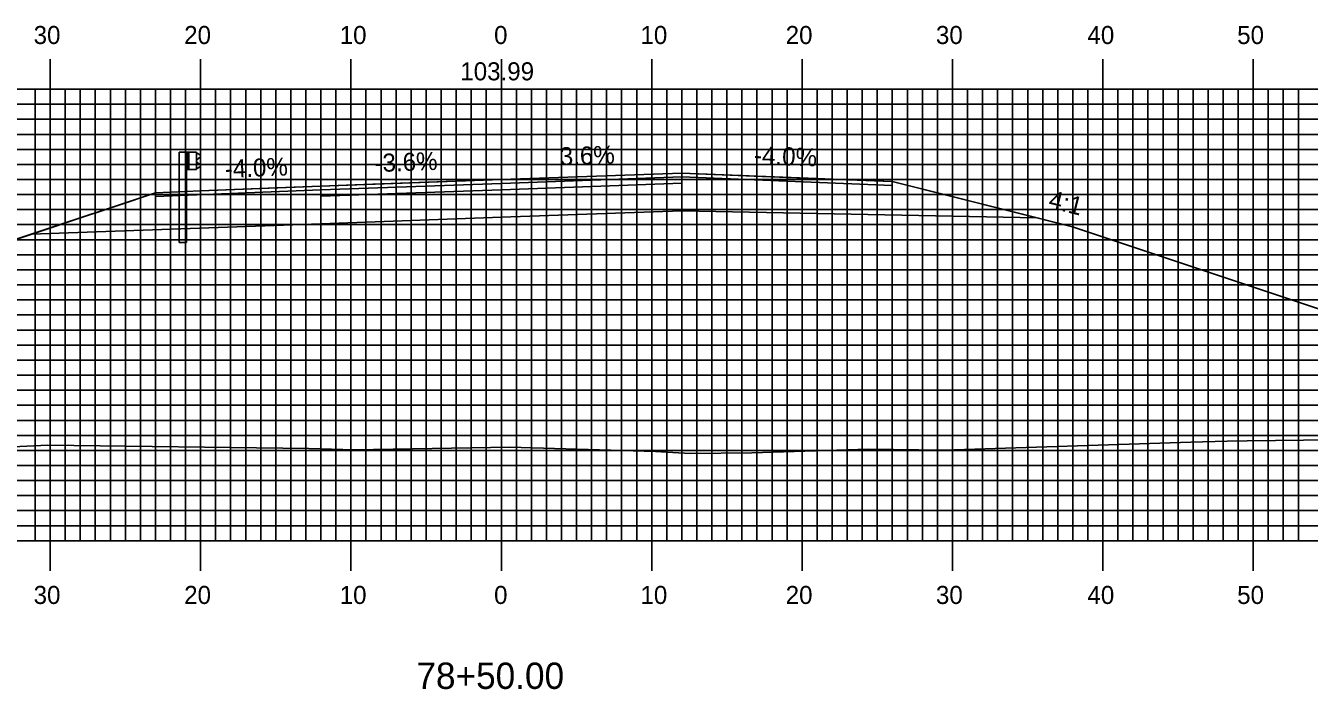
# Model space of a CAD drawing. Extents: x 1762184 to 1762528, y 442591 to 442811.
# Drawn here: x 1762318.6 to 1762404, y 442648.8 to 442692.9 of the extents above; entities that cross this region are included whole.
import ezdxf

# ---------------------------------------------------------------- set-up
doc = ezdxf.new("R2010")
doc.units = 0
for name, color, linetype in [('ANNOTATION', 7, 'Continuous'), ('D_Guardrail_Beam_Lt', 7, 'Continuous'), ('D_Roadway_Centerline', 7, 'Continuous'), ('D_Roadway_Centerline_Text', 7, 'Continuous'), ('D_Roadway_Edge_Shoulder', 7, 'Continuous'), ('D_Roadway_Edge_TW', 7, 'Continuous'), ('D_Roadway_Pavement', 7, 'Continuous'), ('D_Roadway_SlopeLines', 7, 'Continuous'), ('D_Roadway_SubGrade', 7, 'Continuous'), ('H_V ANNOTATION', 7, 'Continuous'), ('MAJOR', 7, 'Continuous'), ('MINOR', 7, 'Continuous'), ('S_Roadway_Centerline', 7, 'Continuous')]:
    doc.layers.add(name, color=color, linetype=linetype)

msp = doc.modelspace()

# ---------------------------------------------------------------- linework, layer by layer
at = {"layer": 'D_Guardrail_Beam_Lt'}
for p, q in [((1762328.838, 442684.487), (1762328.838, 442678.487)), ((1762329.308, 442684.487), (1762328.838, 442684.487)), ((1762329.996, 442684.487), (1762329.308, 442684.487)), ((1762329.308, 442684.487), (1762329.308, 442683.32)), ((1762329.371, 442684.487), (1762329.371, 442683.32)), ((1762329.475, 442684.487), (1762329.475, 442683.32)), ((1762329.996, 442683.32), (1762329.996, 442684.487)), ((1762329.996, 442684.403), (1762330.07, 442684.389)), ((1762330.086, 442684.382), (1762330.229, 442684.282)), ((1762330.07, 442683.418), (1762329.996, 442683.403)), ((1762330, 442683.938), (1762330, 442683.868)), ((1762330.229, 442684.139), (1762330.034, 442684.003)), ((1762330.034, 442683.804), (1762330.229, 442683.668)), ((1762330.229, 442683.524), (1762330.086, 442683.424)), ((1762329.308, 442683.32), (1762329.996, 442683.32)), ((1762329.329, 442678.487), (1762329.329, 442683.32)), ((1762329.329, 442678.487), (1762328.838, 442678.487))]:
    msp.add_line(p, q, dxfattribs=at)
for centre, major_axis, start_param, end_param in [((1762330.062, 442684.348), (0.0417, 0), 0.959931, 1.376053), ((1762330.179, 442684.21), (0.0877, 0), 5.323254, 7.243116), ((1762330.079, 442683.938), (-0.0789, 0), 5.323254, 6.283185), ((1762330.079, 442683.868), (-0.0789, 0), 6.283185, 7.243116), ((1762330.062, 442683.458), (0.0417, 0), 4.907132, 5.323254), ((1762330.179, 442683.596), (0.0877, 0), 5.323254, 7.243116)]:
    msp.add_ellipse(centre, major_axis=major_axis, ratio=0.995501, start_param=start_param, end_param=end_param, dxfattribs=at)
at = {"layer": 'D_Roadway_Centerline'}
msp.add_lwpolyline([(1762276.259, 442664.78), (1762276.276, 442664.786), (1762319.006, 442679.029), (1762324.627, 442680.903), (1762327.264, 442681.783), (1762327.266, 442681.783), (1762330.267, 442681.903), (1762330.268, 442681.903), (1762335.325, 442682.106), (1762338.267, 442682.223), (1762341.123, 442682.326), (1762350.261, 442682.655), (1762350.266, 442682.655), (1762362.262, 442683.087), (1762362.266, 442683.087), (1762362.27, 442683.087), (1762367.62, 442682.873), (1762376.242, 442682.527), (1762376.249, 442682.527), (1762385.899, 442680.115), (1762385.903, 442680.114), (1762388.248, 442679.528), (1762388.25, 442679.527), (1762428.322, 442666.17)], dxfattribs=at)
at = {"layer": 'D_Roadway_Edge_Shoulder'}
for points in [[(1762362.266, 442683.087), (1762376.249, 442682.527), (1762376.249, 442682.277), (1762362.266, 442682.837)], [(1762338.267, 442682.223), (1762330.267, 442681.903), (1762330.267, 442681.903), (1762327.266, 442681.783), (1762327.266, 442681.533), (1762338.267, 442681.973)]]:
    msp.add_lwpolyline(points, close=True, dxfattribs=at)
at = {"layer": 'D_Roadway_Edge_TW'}
msp.add_lwpolyline([(1762338.267, 442681.973), (1762338.267, 442682.223), (1762350.266, 442682.655), (1762362.266, 442683.087), (1762362.266, 442682.837), (1762350.266, 442682.405)], close=True, dxfattribs=at)
at = {"layer": 'D_Roadway_Pavement'}
msp.add_lwpolyline([(1762338.267, 442681.556), (1762338.267, 442681.973), (1762350.266, 442682.405), (1762362.266, 442682.837), (1762362.266, 442682.42), (1762350.266, 442681.988)], close=True, dxfattribs=at)
for points in [[(1762362.266, 442682.837), (1762362.266, 442682.42)], [(1762338.267, 442681.973), (1762338.267, 442681.556)]]:
    msp.add_lwpolyline(points, dxfattribs=at)
at = {"layer": 'D_Roadway_SlopeLines'}
for points in [[(1762327.266, 442681.783), (1762276.259, 442664.78)], [(1762376.249, 442682.527), (1762388.249, 442679.527), (1762428.33, 442666.167)]]:
    msp.add_lwpolyline(points, dxfattribs=at)
at = {"layer": 'D_Roadway_SubGrade'}
for points in [[(1762338.267, 442679.723), (1762338.267, 442681.973), (1762338.267, 442681.556), (1762350.266, 442681.988), (1762362.266, 442682.42), (1762362.266, 442682.837), (1762362.266, 442680.587), (1762350.266, 442680.155)], [(1762362.266, 442682.42), (1762362.266, 442682.837), (1762376.249, 442682.277), (1762376.249, 442682.527), (1762385.903, 442680.114), (1762362.266, 442680.587)], [(1762338.267, 442681.556), (1762338.267, 442681.973), (1762327.266, 442681.533), (1762327.266, 442681.783), (1762319.006, 442679.029), (1762338.267, 442679.723)]]:
    msp.add_lwpolyline(points, close=True, dxfattribs=at)
at = {"layer": 'MAJOR'}
for p, q in [((1762320.266, 442690.669), (1762320.266, 442688.665)), ((1762330.266, 442690.669), (1762330.266, 442688.665)), ((1762340.266, 442690.669), (1762340.266, 442688.665)), ((1762350.266, 442690.669), (1762350.266, 442688.665)), ((1762360.266, 442690.669), (1762360.266, 442688.665)), ((1762370.266, 442690.669), (1762370.266, 442688.665)), ((1762380.266, 442690.669), (1762380.266, 442688.665)), ((1762390.266, 442690.669), (1762390.266, 442688.665)), ((1762400.266, 442690.669), (1762400.266, 442688.665)), ((1762210.266, 442688.665), (1762490.266, 442688.665)), ((1762210.266, 442688.665), (1762490.266, 442688.665)), ((1762320.266, 442658.665), (1762320.266, 442688.665)), ((1762330.266, 442658.665), (1762330.266, 442688.665)), ((1762340.266, 442658.665), (1762340.266, 442688.665)), ((1762350.266, 442658.665), (1762350.266, 442688.665)), ((1762360.266, 442658.665), (1762360.266, 442688.665)), ((1762370.266, 442658.665), (1762370.266, 442688.665)), ((1762380.266, 442658.665), (1762380.266, 442688.665)), ((1762390.266, 442658.665), (1762390.266, 442688.665)), ((1762400.266, 442658.665), (1762400.266, 442688.665)), ((1762210.266, 442683.665), (1762490.266, 442683.665)), ((1762210.266, 442678.665), (1762490.266, 442678.665)), ((1762210.266, 442673.665), (1762490.266, 442673.665)), ((1762210.266, 442668.665), (1762490.266, 442668.665)), ((1762210.266, 442663.665), (1762490.266, 442663.665)), ((1762210.266, 442658.665), (1762490.266, 442658.665)), ((1762210.266, 442658.665), (1762490.266, 442658.665)), ((1762320.266, 442656.661), (1762320.266, 442658.665)), ((1762330.266, 442656.661), (1762330.266, 442658.665)), ((1762340.266, 442656.661), (1762340.266, 442658.665)), ((1762350.266, 442656.661), (1762350.266, 442658.665)), ((1762360.266, 442656.661), (1762360.266, 442658.665)), ((1762370.266, 442656.661), (1762370.266, 442658.665)), ((1762380.266, 442656.661), (1762380.266, 442658.665)), ((1762390.266, 442656.661), (1762390.266, 442658.665)), ((1762400.266, 442656.661), (1762400.266, 442658.665))]:
    msp.add_line(p, q, dxfattribs=at)
at = {"layer": 'MINOR'}
for p, q in [((1762319.266, 442658.665), (1762319.266, 442688.665)), ((1762321.266, 442658.665), (1762321.266, 442688.665)), ((1762322.266, 442658.665), (1762322.266, 442688.665)), ((1762323.266, 442658.665), (1762323.266, 442688.665)), ((1762324.266, 442658.665), (1762324.266, 442688.665)), ((1762325.266, 442658.665), (1762325.266, 442688.665)), ((1762326.266, 442658.665), (1762326.266, 442688.665)), ((1762327.266, 442658.665), (1762327.266, 442688.665)), ((1762328.266, 442658.665), (1762328.266, 442688.665)), ((1762329.266, 442658.665), (1762329.266, 442688.665)), ((1762331.266, 442658.665), (1762331.266, 442688.665)), ((1762332.266, 442658.665), (1762332.266, 442688.665)), ((1762333.266, 442658.665), (1762333.266, 442688.665)), ((1762334.266, 442658.665), (1762334.266, 442688.665)), ((1762335.266, 442658.665), (1762335.266, 442688.665)), ((1762336.266, 442658.665), (1762336.266, 442688.665)), ((1762337.266, 442658.665), (1762337.266, 442688.665)), ((1762338.266, 442658.665), (1762338.266, 442688.665)), ((1762339.266, 442658.665), (1762339.266, 442688.665)), ((1762341.266, 442658.665), (1762341.266, 442688.665)), ((1762342.266, 442658.665), (1762342.266, 442688.665)), ((1762343.266, 442658.665), (1762343.266, 442688.665)), ((1762344.266, 442658.665), (1762344.266, 442688.665)), ((1762345.266, 442658.665), (1762345.266, 442688.665)), ((1762346.266, 442658.665), (1762346.266, 442688.665)), ((1762347.266, 442658.665), (1762347.266, 442688.665)), ((1762348.266, 442658.665), (1762348.266, 442688.665)), ((1762349.266, 442658.665), (1762349.266, 442688.665)), ((1762351.266, 442658.665), (1762351.266, 442688.665)), ((1762352.266, 442658.665), (1762352.266, 442688.665)), ((1762353.266, 442658.665), (1762353.266, 442688.665)), ((1762354.266, 442658.665), (1762354.266, 442688.665)), ((1762355.266, 442658.665), (1762355.266, 442688.665)), ((1762356.266, 442658.665), (1762356.266, 442688.665)), ((1762357.266, 442658.665), (1762357.266, 442688.665)), ((1762358.266, 442658.665), (1762358.266, 442688.665)), ((1762359.266, 442658.665), (1762359.266, 442688.665)), ((1762361.266, 442658.665), (1762361.266, 442688.665)), ((1762362.266, 442658.665), (1762362.266, 442688.665)), ((1762363.266, 442658.665), (1762363.266, 442688.665)), ((1762364.266, 442658.665), (1762364.266, 442688.665)), ((1762365.266, 442658.665), (1762365.266, 442688.665)), ((1762366.266, 442658.665), (1762366.266, 442688.665)), ((1762367.266, 442658.665), (1762367.266, 442688.665)), ((1762368.266, 442658.665), (1762368.266, 442688.665)), ((1762369.266, 442658.665), (1762369.266, 442688.665)), ((1762371.266, 442658.665), (1762371.266, 442688.665)), ((1762372.266, 442658.665), (1762372.266, 442688.665)), ((1762373.266, 442658.665), (1762373.266, 442688.665)), ((1762374.266, 442658.665), (1762374.266, 442688.665)), ((1762375.266, 442658.665), (1762375.266, 442688.665)), ((1762376.266, 442658.665), (1762376.266, 442688.665)), ((1762377.266, 442658.665), (1762377.266, 442688.665)), ((1762378.266, 442658.665), (1762378.266, 442688.665)), ((1762379.266, 442658.665), (1762379.266, 442688.665)), ((1762381.266, 442658.665), (1762381.266, 442688.665)), ((1762382.266, 442658.665), (1762382.266, 442688.665)), ((1762383.266, 442658.665), (1762383.266, 442688.665)), ((1762384.266, 442658.665), (1762384.266, 442688.665)), ((1762385.266, 442658.665), (1762385.266, 442688.665)), ((1762386.266, 442658.665), (1762386.266, 442688.665)), ((1762387.266, 442658.665), (1762387.266, 442688.665)), ((1762388.266, 442658.665), (1762388.266, 442688.665)), ((1762389.266, 442658.665), (1762389.266, 442688.665)), ((1762391.266, 442658.665), (1762391.266, 442688.665)), ((1762392.266, 442658.665), (1762392.266, 442688.665)), ((1762393.266, 442658.665), (1762393.266, 442688.665)), ((1762394.266, 442658.665), (1762394.266, 442688.665)), ((1762395.266, 442658.665), (1762395.266, 442688.665)), ((1762396.266, 442658.665), (1762396.266, 442688.665)), ((1762397.266, 442658.665), (1762397.266, 442688.665)), ((1762398.266, 442658.665), (1762398.266, 442688.665)), ((1762399.266, 442658.665), (1762399.266, 442688.665)), ((1762401.266, 442658.665), (1762401.266, 442688.665)), ((1762402.266, 442658.665), (1762402.266, 442688.665)), ((1762403.266, 442658.665), (1762403.266, 442688.665)), ((1762210.266, 442687.665), (1762490.266, 442687.665)), ((1762210.266, 442686.665), (1762490.266, 442686.665)), ((1762210.266, 442685.665), (1762490.266, 442685.665)), ((1762210.266, 442684.665), (1762490.266, 442684.665)), ((1762210.266, 442682.665), (1762490.266, 442682.665)), ((1762210.266, 442681.665), (1762490.266, 442681.665)), ((1762210.266, 442680.665), (1762490.266, 442680.665)), ((1762210.266, 442679.665), (1762490.266, 442679.665)), ((1762210.266, 442677.665), (1762490.266, 442677.665)), ((1762210.266, 442676.665), (1762490.266, 442676.665)), ((1762210.266, 442675.665), (1762490.266, 442675.665)), ((1762210.266, 442674.665), (1762490.266, 442674.665)), ((1762210.266, 442672.665), (1762490.266, 442672.665)), ((1762210.266, 442671.665), (1762490.266, 442671.665)), ((1762210.266, 442670.665), (1762490.266, 442670.665)), ((1762210.266, 442669.665), (1762490.266, 442669.665)), ((1762210.266, 442667.665), (1762490.266, 442667.665)), ((1762210.266, 442666.665), (1762490.266, 442666.665)), ((1762210.266, 442665.665), (1762490.266, 442665.665)), ((1762210.266, 442664.665), (1762490.266, 442664.665)), ((1762210.266, 442662.665), (1762490.266, 442662.665)), ((1762210.266, 442661.665), (1762490.266, 442661.665)), ((1762210.266, 442660.665), (1762490.266, 442660.665)), ((1762210.266, 442659.665), (1762490.266, 442659.665))]:
    msp.add_line(p, q, dxfattribs=at)
at = {"layer": 'S_Roadway_Centerline'}
msp.add_lwpolyline([(1762268.086, 442664.554), (1762279.617, 442664.873), (1762287.462, 442665.125), (1762291.847, 442665.205), (1762299.238, 442664.881), (1762303.668, 442664.542), (1762309.767, 442664.735), (1762315.453, 442664.795), (1762320.104, 442665.005), (1762337.476, 442664.8), (1762340.488, 442664.701), (1762350.842, 442664.877), (1762360.523, 442664.604), (1762362.812, 442664.46), (1762366.926, 442664.515), (1762374.676, 442664.747), (1762379.68, 442664.692), (1762396.124, 442665.222), (1762398.524, 442665.288), (1762399.871, 442665.298), (1762409.23, 442665.406)], dxfattribs=at)

# ---------------------------------------------------------------- texts
at = {"layer": 'ANNOTATION'}
for s, rotation, p in [('-3.6%', 2.06186, (1762341.85, 442683.154)), ('3.6%', 2.06172, (1762354.171, 442683.597)), ('-4.0%', 357.70666, (1762367.048, 442683.697)), ('-4.0%', 2.29066, (1762331.899, 442682.77)), ('4:1', 345.95392, (1762386.582, 442680.806))]:
    msp.add_text(s, height=1.2, rotation=rotation, dxfattribs=at).set_placement(p)
at = {"layer": 'D_Roadway_Centerline'}
for s, p in [('C', (1762350.261, 442682.655)), ('L', (1762350.266, 442682.648))]:
    msp.add_text(s, height=0.0146, dxfattribs=at).set_placement(p)
at = {"layer": 'D_Roadway_Centerline_Text'}
msp.add_text('103.99', height=1.2, dxfattribs=at).set_placement((1762347.537, 442689.252))
at = {"layer": 'H_V ANNOTATION'}
for s, height, p in [('30', 1.2, (1762319.164, 442691.665)), ('20', 1.2, (1762329.174, 442691.665)), ('10', 1.2, (1762339.517, 442691.665)), ('0', 1.2, (1762349.784, 442691.665)), ('10', 1.2, (1762359.517, 442691.665)), ('20', 1.2, (1762369.174, 442691.665)), ('30', 1.2, (1762379.164, 442691.665)), ('40', 1.2, (1762389.239, 442691.665)), ('50', 1.2, (1762399.196, 442691.665)), ('30', 1.2, (1762319.164, 442654.465)), ('20', 1.2, (1762329.174, 442654.465)), ('10', 1.2, (1762339.517, 442654.465)), ('0', 1.2, (1762349.784, 442654.465)), ('10', 1.2, (1762359.517, 442654.465)), ('20', 1.2, (1762369.174, 442654.465)), ('30', 1.2, (1762379.164, 442654.465)), ('40', 1.2, (1762389.239, 442654.465)), ('50', 1.2, (1762399.196, 442654.465)), ('78+50.00', 1.75, (1762344.616, 442648.821))]:
    msp.add_text(s, height=height, dxfattribs=at).set_placement(p)

doc.saveas('drawing.dxf')
